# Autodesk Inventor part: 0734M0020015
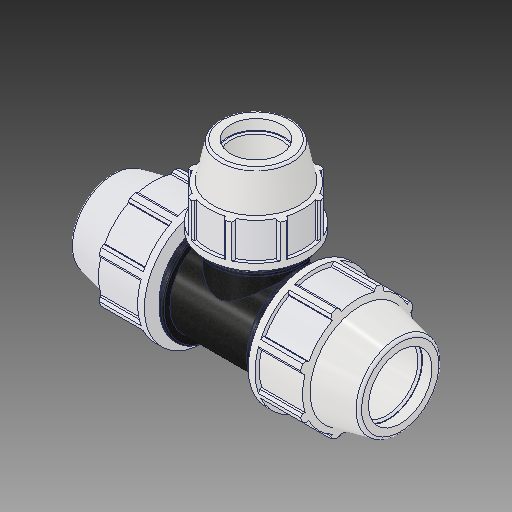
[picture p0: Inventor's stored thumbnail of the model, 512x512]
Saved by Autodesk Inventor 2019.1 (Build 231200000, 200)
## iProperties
Created: 2017-02
Part Number: 0734M0020015
Material: PVC-Piping
Description: PLASSON REDUCING TEE 2'' - 1 1/2'' - 2''
Document SubType Name: Modeling
Designer: KIM
Mass: 92.6774 g
Surface Area: 199.44 cm^2
Volume: 66.1981 cm^3
Density: 1.4 g/cm^3
Appearance: PTFE
Author: Кирилл
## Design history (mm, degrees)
derived "0734M0.ipt"
feature "Solid1::0734M0.ipt"
feature "Solid2::0734M0.ipt"
tag "TaggingFeature1"
body "Solid1"
other parameters: "d2" = 60.1, "d4" = 11.37708, "d5" = 38.227, "d7" = 113.03, "d11" = 4.55083, "d13" = 120 deg, "d14" = 78.13, "d15" = 12 deg, "d16" = 98.3361, "d18" = 3.005, "d19" = 35 deg, "d20" = 17.5 deg, "d21" = 105.1179, "d23" = 0, "d25" = 360 deg, "d27" = 2.2606, "d33" = 1.202, "d42" = 49.149, "d43" = 3.3909, "d46" = 1.803, "d67" = 84.7725, "d76" = 48.1, "d77" = 96.012, "d78" = 12 deg, "d79" = 134.874, "d80" = 120 deg, "d81" = 67.34, "d82" = 11.2395, "d87" = 4.4958, "d89" = 33.7185, "d90" = 40.4622, "d96" = 22.75417, "d98" = 89.29116, "d99" = 35 deg, "d100" = 17.5 deg, "d102" = 0, "d103" = 1.92024, "d107" = 360 deg, "d109" = 1.443, "d112" = 2.405, "d113" = 6.4008, "d114" = 0, "d117" = 273.05, "d118" = 83.53044, "d126" = 54.09, "d127" = 108.966, "d131" = 5.39496, "d132" = 43.29, "d133" = 92.964, "d135" = 0, "d138" = 5.461, "d143" = 0, "d148" = 72.009, "d168" = 54.09, "d170" = 0, "d171" = 48.1, "d173" = 0, "d176" = 6.4008, "d177" = 0, "d_" = 60.1, "E_" = 113.03, "A_" = 134.874, "l_" = 108.966, "E_1" = 96.012, "l_1" = 92.964, "d_1" = 48.1, "H_" = 273.05
